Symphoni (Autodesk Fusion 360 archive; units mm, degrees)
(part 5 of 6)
sketch "Sketch36" plane through (0, 0, -41.2) normal (0, 0, -1) x axis (1, 0, 0)
  line L1 (80, 22.1729) -> (80, -17.8271)
  line L2 (40, 22.1729) -> (80, 22.1729)
  line L3 (40, -17.8271) -> (40, 22.1729)
  line L4 (80, -17.8271) -> (40, -17.8271)
  line L5 (31.4652, -4.8271) -> (42.4652, -4.8271)
  line L6 (31.4652, 9.1729) -> (31.4652, -4.8271)
  line L7 (42.4652, 9.1729) -> (31.4652, 9.1729)
  line L8 (42.4652, 13.4229) -> (42.4652, 9.1729)
  line L9 (76.9652, 13.4229) -> (42.4652, 13.4229)
  line L10 (78.9652, -7.0771) -> (78.9652, 11.4229)
  line L11 (42.4652, -9.0771) -> (76.9652, -9.0771)
  line L12 (42.4652, -4.8271) -> (42.4652, -9.0771)
  line L13 (34.9931, -0.7865) -> (34.9931, -0.3271)
  line L14 (37.9931, -0.7865) -> (34.9931, -0.7865)
  line L15 (37.9931, 5.2135) -> (37.9931, -0.7865)
  line L16 (34.9931, 5.2135) -> (37.9931, 5.2135)
  line L17 (34.9931, 4.6729) -> (34.9931, 5.2135)
  line L18 (33.9931, 4.6729) -> (34.9931, 4.6729)
  line L19 (33.9931, -0.3271) -> (33.9931, 4.6729)
  line L20 (34.9931, -0.3271) -> (33.9931, -0.3271)
  arc A1 centre (76.9652, 11.4229) radius 2 clockwise from (76.9652, 13.4229) to (78.9652, 11.4229)
  arc A2 centre (76.9652, -7.0771) radius 2 clockwise from (78.9652, -7.0771) to (76.9652, -9.0771)
  circle C1 centre (67.9652, 2.1729) radius 3.5
  circle C2 centre (56.9652, 2.1729) radius 2
  circle C3 centre (61.9652, 11.9229) radius 0.75
  circle C4 centre (76.9652, 11.4229) radius 1
  circle C5 centre (76.9652, -7.0771) radius 1
  circle C6 centre (61.9652, -7.5771) radius 0.75
  arc A3 centre (44.4652, -7.0771) radius 1.25 clockwise from (45.2016, -6.0671) to (44.1373, -5.8709)
  arc A4 centre (45.0652, -3.8212) radius 2.25 clockwise from (46.2076, -5.7597) to (45.2016, -6.0671)
  arc A5 centre (47.4652, -6.5771) radius 1.5 clockwise from (46.8283, -5.2191) to (46.2076, -5.7597)
  arc A6 centre (45.0652, -3.8212) radius 2.25 clockwise from (44.1373, -5.8709) to (46.8283, -5.2191)
  arc A7 centre (44.4652, 11.4229) radius 1.25 clockwise from (44.1373, 10.2167) to (45.2016, 10.4128)
  arc A8 centre (45.0652, 8.1669) radius 2.25 clockwise from (46.8283, 9.5648) to (44.1373, 10.2167)
  arc A9 centre (47.4652, 10.9229) radius 1.5 clockwise from (46.2076, 10.1054) to (46.8283, 9.5648)
  arc A10 centre (45.0652, 8.1669) radius 2.25 clockwise from (45.2016, 10.4128) to (46.2076, 10.1054)
  arc A11 centre (47.4652, 10.9229) radius 1.65 clockwise from (46.0818, 10.0236) to (46.7646, 9.429)
  arc A12 centre (44.4652, 11.4229) radius 1.4 clockwise from (44.0979, 10.0719) to (45.29, 10.2916)
  circle C7 centre (76.9652, -7.0771) radius 1.2
  circle C8 centre (76.9652, 11.4229) radius 1.2
  circle C9 centre (47.4652, 10.9229) radius 1.65
  circle C10 centre (44.4652, 11.4229) radius 1.4
  circle C11 centre (44.4652, 11.4229) radius 1.4
  circle C12 centre (47.4652, -6.5771) radius 1.65
  circle C13 centre (44.4652, -7.0771) radius 1.4
  circle C14 centre (81.4652, 2.1729) radius 1.25
  arc A13 centre (44.4652, -7.0771) radius 1.4 clockwise from (45.5356, -6.1747) to (45.8228, -6.7351)
  arc A14 centre (45.0652, -3.8212) radius 2.4 clockwise from (45.894, -6.0736) to (45.5356, -6.1747)
  arc A15 centre (47.4652, -6.5771) radius 1.65 clockwise from (45.8228, -6.7351) to (45.894, -6.0736)
  arc A16 centre (44.4652, -7.0771) radius 1.4 clockwise from (45.8604, -6.9604) to (43.7869, -5.8524)
  arc A17 centre (47.4652, -6.5771) radius 1.65 clockwise from (47.1824, -4.9516) to (45.8604, -6.9604)
  arc A18 centre (45.0652, -3.8212) radius 2.4 clockwise from (43.7869, -5.8524) to (47.1824, -4.9516)
  point P45 (46.0818, 10.0236)
  point P52 (45.894, -6.0736)
  point P54 (43.7869, -5.8524)
  concentric A9 C9
  coincident P45 C9
  concentric A7 C10
  concentric A7 C11
  concentric A5 C12
  coincident P52 C12
  concentric A3 C13
  coincident P54 C13
  dimension "d250" = 0.15
  dimension "d251" = 0.15
  dimension "d252" = 0.15
  dimension "d253" = 0.2
  dimension "d254" = 0.2
extrude "Extrude3" cut sketch "Sketch36" profile of C4 C5 A3 A4 A5 A6 A7 A8 A9 A10 A11 A12 A16 A17 C7 C8 C9 C10 C11 C12 C13 against normal blind 6
extrude "Extrude4" cut sketch "Sketch36" profile of C14 against normal blind 5
sketch "Sketch37" plane through (0, 0, -59.9956) normal (0, 0, 1) x axis (-1, 0, 0)
  line L1 (-85, 22.1729) -> (-85, -17.8271)
  line L2 (-96.2951, 22.1729) -> (-85, 22.1729)
  line L3 (-96.2951, -17.8271) -> (-96.2951, 22.1729)
  line L4 (-85, -17.8271) -> (-96.2951, -17.8271)
  circle C1 centre (-90.6476, 2.1729) radius 2.1
  circle C2 centre (-90.6476, 2.1729) radius 3
  concentric C1 C2
  dimension "d259" diameter C1 = 4.2
  dimension "d260" diameter C2 = 6
extrude "Extrude5" cut sketch "Sketch37" profile of C1 against normal blind 7
extrude "Extrude6" cut sketch "Sketch37" profile of C1 C2 against normal blind 1
split "Split2"
remove_body "RemoveBody6"
split "Split3"
sketch "Sketch38" plane through (0, 0, -65) normal (0, 0, -1) x axis (1, 0, 0)
  line L1 (11.5885, -27.6714) -> (11.5885, -22)
  line L2 (-11.2525, -22) -> (-11.2525, -27.8097)
  line L3 (11.5885, -22) -> (-11.2525, -22)
  circle C1 centre (-11.7533, -6.7858) radius 2.7
  circle C2 centre (11.7533, -6.7858) radius 2.7
  circle C3 centre (0, 13.5716) radius 2.7
  arc A1 centre (0, 0) radius 30 clockwise from (-11.2525, -27.8097) to (11.5885, -27.6714)
  circle C4 centre (0, 0) radius 30.3693
  point P1 (0, 0)
  point P10 (0, 0)
  coincident P1 P10
extrude "Extrude21" cut sketch "Sketch38" profile of C1 C2 C3 L1 A1 L2 L3 against normal blind 15
offset_faces "OffsetFaces3" distance -2
combine "Combine1"
fillet "Fillet1" radius 2
fillet "Fillet2" radius 2.5
fillet "Fillet3" radius 2.5
sketch "Sketch39" plane through (0, -22.1729, 0) normal (0, -1, 0) x axis (1, 0, 0)
  line L1 (96.2951, -64.9956) -> (82.5, -64.9956)
  line L2 (96.2951, -62.4956) -> (96.2951, -64.9956)
  line L3 (87, -59.9956) -> (93.7951, -59.9956)
  line L4 (85, -36.6938) -> (85, -57.9956)
  line L5 (30, -36.6938) -> (85, -36.6938)
  line L6 (20.208, -64.4069) -> (30, -36.6938)
  line L7 (20.208, -64.9956) -> (20.208, -64.4069)
  line L8 (37.5, -64.9956) -> (20.208, -64.9956)
  line L9 (40, -43.7) -> (40, -62.4956)
  line L10 (77.5, -41.2) -> (42.5, -41.2)
  line L11 (80, -62.4956) -> (80, -43.7)
  line L12 (47.9289, -41.2) -> (40, -49.3404)
  line L13 (80.0516, -43.7) -> (40, -43.7)
  line L14 (80.0516, -36.6938) -> (80.0516, -43.7)
  line L15 (40, -36.6938) -> (80.0516, -36.6938)
  line L16 (40, -43.7) -> (40, -36.6938)
  line L17 (60.0258, -43.7) -> (60.0258, -36.6938)
  line L18 (72.1227, -41.2) -> (80.0516, -49.3404)
  arc A1 centre (82.5, -62.4956) radius 2.5 clockwise from (82.5, -64.9956) to (80, -62.4956)
  arc A2 centre (93.7951, -62.4956) radius 2.5 clockwise from (93.7951, -59.9956) to (96.2951, -62.4956)
  arc A3 centre (87, -57.9956) radius 2 clockwise from (87, -59.9956) to (85, -57.9956)
  arc A4 centre (37.5, -62.4956) radius 2.5 clockwise from (40, -62.4956) to (37.5, -64.9956)
  arc A5 centre (42.5, -43.7) radius 2.5 clockwise from (40, -43.7) to (42.5, -41.2)
  arc A6 centre (77.5, -43.7) radius 2.5 clockwise from (77.5, -41.2) to (80, -43.7)
  circle C1 centre (32, -60) radius 1.6
  point P26 (40, -49.3404)
  point P27 (47.9289, -41.2)
  point P30 (80.0516, -36.6938)
  point P19 (40, -43.7)
  point P28 (40, -43.7)
  point P32 (60.0258, -36.6938)
  point P33 (60.0258, -43.7)
  point P34 (80.0516, -49.3404)
  point P35 (72.1227, -41.2)
  coincident L9 P26
  coincident L10 P27
  horizontal L13
  vertical L14
  horizontal L15
  vertical L16
  coincident L5 P30
  coincident P19 P28
  midpoint L15 P32
  midpoint L13 P33
  symmetric P26 L17 P34
  symmetric P27 L17 P35
extrude "Extrude22" new body sketch "Sketch39" profile of L9 A5 L10 A6 L11 L12 L13 L18 against normal blind 9
combine "Combine1"
offset_faces "OffsetFaces2" distance -2.1
work_plane "WorkPlane6"
work_plane "WorkPlane8" AlongDistance -5
sketch "Sketch40" plane through (0, -17.1729, 0) normal (0, -1, 0) x axis (-1, 0, 0)
  line L1 (-32, 56.7668) -> (-34.8, 58.3834)
  line L2 (-29.2, 58.3834) -> (-32, 56.7668)
  line L3 (-29.2, 61.6166) -> (-29.2, 58.3834)
  line L4 (-32, 63.2332) -> (-29.2, 61.6166)
  line L5 (-34.8, 61.6166) -> (-32, 63.2332)
  line L6 (-34.8, 58.3834) -> (-34.8, 61.6166)
  line L7 (-48.1073, 56.7668) -> (-32, 56.7668)
  line L8 (-48.1073, 63.2332) -> (-48.1073, 56.7668)
  line L9 (-32, 63.2332) -> (-48.1073, 63.2332)
  line L10 (-32, 56.7668) -> (-32, 63.2332)
  circle C1 centre (-32, 60) radius 1.6
  point P2 (-32, 60)
  point P9 (-32, 60)
  coincident P2 P9
  vertical L3
  horizontal L7
  vertical L8
  horizontal L9
  vertical L10
  dimension "d279" distance L3 L6 = 5.6
extrude "Extrude8" cut sketch "Sketch40" distance 2.62
mirror "Mirror1" mirrorStitchTolerance 0.1
sketch "Sketch41" plane through (0, 0, -36.6938) normal (0, 0, 1) x axis (-1, 0, 0)
  line L1 (-30, 0) -> (-30, -17.8271)
  line L2 (-30, 22.1729) -> (-30, 0)
  line L3 (-85, 22.1729) -> (-30, 22.1729)
  line L4 (-85, -17.8271) -> (-85, 22.1729)
  line L5 (-30, -17.8271) -> (-85, -17.8271)
  line L6 (-31.4652, -4.8271) -> (-42.4652, -4.8271)
  line L7 (-31.4652, 9.1729) -> (-31.4652, -4.8271)
  line L8 (-42.4652, 9.1729) -> (-31.4652, 9.1729)
  line L9 (-42.4652, 13.4229) -> (-42.4652, 9.1729)
  line L10 (-76.9652, 13.4229) -> (-42.4652, 13.4229)
  line L11 (-78.9652, -7.0771) -> (-78.9652, 11.4229)
  line L12 (-42.4652, -9.0771) -> (-76.9652, -9.0771)
  line L13 (-42.4652, -4.8271) -> (-42.4652, -9.0771)
  line L14 (-34.9931, -0.7865) -> (-34.9931, -0.3271)
  line L15 (-37.9931, -0.7865) -> (-34.9931, -0.7865)
  line L16 (-37.9931, 5.2135) -> (-37.9931, -0.7865)
  line L17 (-34.9931, 5.2135) -> (-37.9931, 5.2135)
  line L18 (-34.9931, 4.6729) -> (-34.9931, 5.2135)
  line L19 (-33.9931, 4.6729) -> (-34.9931, 4.6729)
  line L20 (-33.9931, -0.3271) -> (-33.9931, 4.6729)
  line L21 (-34.9931, -0.3271) -> (-33.9931, -0.3271)
  line L22 (-79.6652, -7.0771) -> (-79.6652, 11.4229)
  line L23 (-41.7652, -9.7771) -> (-76.9652, -9.7771)
  line L24 (-41.7652, -5.5271) -> (-41.7652, -9.7771)
  line L25 (-30.7652, -5.5271) -> (-41.7652, -5.5271)
  line L26 (-30.7652, 9.8729) -> (-30.7652, -5.5271)
  line L27 (-41.7652, 9.8729) -> (-30.7652, 9.8729)
  line L28 (-41.7652, 14.1229) -> (-41.7652, 9.8729)
  line L29 (-76.9652, 14.1229) -> (-41.7652, 14.1229)
  line L30 (-81.9652, -7.0771) -> (-81.9652, 11.4229)
  line L31 (-39.4652, -12.0771) -> (-76.9652, -12.0771)
  line L32 (-39.4652, -7.8271) -> (-39.4652, -12.0771)
  line L33 (-28.4652, -7.8271) -> (-39.4652, -7.8271)
  line L34 (-28.4652, 12.1729) -> (-28.4652, -7.8271)
  line L35 (-39.4652, 12.1729) -> (-28.4652, 12.1729)
  line L36 (-39.4652, 16.4229) -> (-39.4652, 12.1729)
  line L37 (-76.9652, 16.4229) -> (-39.4652, 16.4229)
  line L38 (-81.9652, 5.8898) -> (-79.6652, 5.8898)
  line L39 (-81.9652, -1.9652) -> (-81.9652, 5.8898)
  line L40 (-79.6652, -1.9652) -> (-81.9652, -1.9652)
  line L41 (-79.6652, 5.8898) -> (-79.6652, -1.9652)
  line L42 (-39.4652, -12.0771) -> (-39.4652, 16.4229)
  circle C1 centre (-81.4652, 2.1729) radius 1.25
  circle C2 centre (-76.9652, 11.4229) radius 1.2
  arc A1 centre (-47.4652, -6.5771) radius 1.65 clockwise from (-45.8604, -6.9604) to (-45.8228, -6.7351)
  arc A2 centre (-44.4652, -7.0771) radius 1.4 clockwise from (-45.8228, -6.7351) to (-45.8604, -6.9604)
  arc A3 centre (-44.4652, 11.4229) radius 1.4 clockwise from (-45.8604, 11.3061) to (-45.8228, 11.0809)
  arc A4 centre (-47.4652, 10.9229) radius 1.65 clockwise from (-45.8228, 11.0809) to (-45.8604, 11.3061)
  circle C3 centre (-76.9652, -7.0771) radius 1.2
  arc A5 centre (-76.9652, 11.4229) radius 2 clockwise from (-78.9652, 11.4229) to (-76.9652, 13.4229)
  arc A6 centre (-76.9652, -7.0771) radius 2 clockwise from (-76.9652, -9.0771) to (-78.9652, -7.0771)
  circle C4 centre (-67.9652, 2.1729) radius 3.5
  circle C5 centre (-56.9652, 2.1729) radius 2
  circle C6 centre (-61.9652, 11.9229) radius 0.75
  circle C7 centre (-76.9652, 11.4229) radius 1
  circle C8 centre (-76.9652, -7.0771) radius 1
  circle C9 centre (-61.9652, -7.5771) radius 0.75
  arc A7 centre (-44.4652, -7.0771) radius 1.25 clockwise from (-44.1373, -5.8709) to (-45.2016, -6.0671)
  arc A8 centre (-45.0652, -3.8212) radius 2.25 clockwise from (-45.2016, -6.0671) to (-46.2076, -5.7597)
  arc A9 centre (-47.4652, -6.5771) radius 1.5 clockwise from (-46.2076, -5.7597) to (-46.8283, -5.2191)
  arc A10 centre (-45.0652, -3.8212) radius 2.25 clockwise from (-46.8283, -5.2191) to (-44.1373, -5.8709)
  arc A11 centre (-44.4652, 11.4229) radius 1.25 clockwise from (-45.2016, 10.4128) to (-44.1373, 10.2167)
  arc A12 centre (-45.0652, 8.1669) radius 2.25 clockwise from (-44.1373, 10.2167) to (-46.8283, 9.5648)
  arc A13 centre (-47.4652, 10.9229) radius 1.5 clockwise from (-46.8283, 9.5648) to (-46.2076, 10.1054)
  arc A14 centre (-45.0652, 8.1669) radius 2.25 clockwise from (-46.2076, 10.1054) to (-45.2016, 10.4128)
  arc A15 centre (-76.9652, -7.0771) radius 2.7 clockwise from (-76.9652, -9.7771) to (-79.6652, -7.0771)
  arc A16 centre (-76.9652, 11.4229) radius 2.7 clockwise from (-79.6652, 11.4229) to (-76.9652, 14.1229)
  arc A17 centre (-76.9652, -7.0771) radius 5 clockwise from (-76.9652, -12.0771) to (-81.9652, -7.0771)
  arc A18 centre (-76.9652, 11.4229) radius 5 clockwise from (-81.9652, 11.4229) to (-76.9652, 16.4229)
  point P82 (-81.9652, -1.9652)
  point P80 (-79.6652, 5.8898)
  horizontal L38
  vertical L39
  horizontal L40
  vertical L41
  coincident L30 P82
  coincident L22 P80
  dimension "d284" = 0.7
  dimension "d285" = 3
extrude "Extrude9" add sketch "Sketch41" profile of A16 A15 L27 L25 L23 L22 L24 L28 L29 L30 A17 A18 L36 L32 L31 L37 L38 L40 L42 along normal blind 1.5
sketch "Sketch42" plane through (42.4652, 0, 0) normal (-1, 0, 0) x axis (0, -1, 0)
  line L1 (13.4229, -36.2) -> (9.1729, -36.2)
  line L2 (13.4229, -27.2) -> (13.4229, -36.2)
  line L3 (9.5319, -34.8072) -> (-6.1234, -34.8072)
  line L4 (9.5319, -39.723) -> (9.5319, -34.8072)
  line L5 (-6.1234, -39.723) -> (9.5319, -39.723)
  line L6 (-6.1234, -34.8072) -> (-6.1234, -39.723)
  arc A1 centre (1.7685, -27.2) radius 11.6544 clockwise from (13.4229, -27.2) to (9.1729, -36.2)
  horizontal L3
  vertical L4
  horizontal L5
  vertical L6
extrude "Extrude10" cut sketch "Sketch42" profile of A1 L1 L3 L4 L5 L6 along normal blind 13
work_plane "WorkPlane9" AlongDistance -28.796
split "Split3"
offset_faces "OffsetFaces1" distance 1.006
combine "Combine2"
combine "Combine2"
sketch "Sketch43" plane through (24.5652, 0, 0) normal (1, 0, 0) x axis (0, 1, 0)
  line L1 (-12.1972, -25.2) -> (-11.1736, -25.2)
  line L2 (-11.1736, -29.2) -> (-12.1972, -29.2)
  curve K1 (5.1979, -34.8072) -> (7.241, -23)
  curve K2 (7.241, -23) -> (4.8434, -19.2)
  line L3 (-9.1891, -19.2) -> (4.8434, -19.2)
  curve K3 (-9.1891, -19.2) -> (-11.5868, -23)
  curve K4 (-11.5868, -23) -> (-9.1891, -35.2)
  line L4 (5.1979, -35.2) -> (-9.1891, -35.2)
  line L5 (5.1979, -34.8072) -> (5.1979, -35.2)
  curve K5 (-11.8666, -22.8918) -> (-9.3174, -35.5)
  curve K6 (-9.3174, -18.9) -> (-11.8666, -22.8918)
  line L6 (-9.3174, -18.9) -> (4.9717, -18.9)
  curve K7 (7.5208, -22.8918) -> (4.9717, -18.9)
  curve K8 (5.4979, -34.9178) -> (7.5208, -22.8918)
  line L7 (5.4979, -34.9178) -> (5.4979, -35.5)
  line L8 (5.4979, -35.5) -> (-9.3174, -35.5)
  arc A1 centre (-11.1736, -27.2) radius 2 clockwise from (-11.1736, -25.2) to (-11.1736, -29.2)
  arc A2 centre (-0.7202, -27.2) radius 11.65 clockwise from (-12.1972, -29.2) to (-12.1972, -25.2)
  point P13 (-9.1891, -35.2)
  point P14 (-9.1891, -35.2)
  point P9 (5.1979, -34.8072)
  point P16 (5.1979, -34.8072)
  coincident P13 P14
  horizontal L4
  coincident P9 P16
  vertical L5
  dimension "d292" = 0.3
extrude "Extrude23" cut sketch "Sketch43" along normal blind 8 and against normal blind 4.5
fillet "Fillet3" radius 5
sketch "Sketch44" plane through (0, 0, -65) normal (0, 0, -1) x axis (1, 0, 0)
  line L1 (40, -27.6271) -> (11.6937, -27.6271)
  line L2 (40, -17.8271) -> (40, -27.6271)
  line L3 (24.1287, -17.8271) -> (40, -17.8271)
  line L4 (-11.2525, -22) -> (-11.2525, -27.8097)
  line L5 (11.5885, -22) -> (-11.2525, -22)
  line L6 (11.5885, -27.6714) -> (11.5885, -22)
  line L7 (0, 35) -> (0, 0)
  curve K1 (-8.9209, 28.6429) -> (-5, 35)
  curve K2 (8.9209, 28.6429) -> (5, 35)
  curve K3 (-5.1872, 34.0384) -> (-4.8128, 35.9616)
  curve K4 (-9.7824, 28.3746) -> (-8.0593, 28.9113)
  curve K5 (5.1872, 34.0384) -> (4.8128, 35.9616)
  curve K6 (9.7824, 28.3746) -> (8.0593, 28.9113)
  curve K7 (-28.6429, -8.9209) -> (-35, -5)
  curve K8 (-28.6429, 8.9209) -> (-35, 5)
  curve K9 (8.9209, -28.6429) -> (5, -35)
  curve K10 (-8.9209, -28.6429) -> (-5, -35)
  circle C1 centre (0, 13.5716) radius 2.7
  circle C2 centre (11.7533, -6.7858) radius 2.7
  circle C3 centre (-11.7533, -6.7858) radius 2.7
  arc A1 centre (0, 0) radius 30 clockwise from (-11.2525, -27.8097) to (24.1287, -17.8271)
  arc A2 centre (0, 0) radius 30 clockwise from (11.6937, -27.6271) to (11.5885, -27.6714)
  circle C4 centre (0, 35) radius 2
  circle C5 centre (0, 35) radius 5
  circle C6 centre (-35, 0) radius 5
  circle C7 centre (-35, 0) radius 2
  circle C8 centre (0, -35) radius 5
  circle C9 centre (0, -35) radius 2
  point P10 (0, 0)
  point P14 (0, 0)
  point P15 (0, 35)
  point P16 (0, 35)
  point P18 (-5, 35)
  point P19 (-8.9209, 28.6429)
  point P20 (5, 35)
  point P21 (8.9209, 28.6429)
  point P22 (-4.8128, 35.9616)
  point P26 (4.8128, 35.9616)
  point P23 (-5.1872, 34.0384)
  point P27 (5.1872, 34.0384)
  point P24 (-8.0593, 28.9113)
  point P28 (8.0593, 28.9113)
  point P25 (-9.7824, 28.3746)
  point P29 (9.7824, 28.3746)
  coincident P10 P14
  vertical L7
  coincident P15 P16
  concentric C4 C5
  tangent A1 C5
  coincident C5 P18
  coincident A1 P19
  tangent A1 K1
  tangent C5 K1
  midpoint P18 K3
  midpoint P19 K4
  symmetric L7 P18 P20
  symmetric L7 P19 P21
  symmetric L7 P22 P26
  symmetric L7 P23 P27
  symmetric L7 P24 P28
  symmetric L7 P25 P29
  dimension "d299" diameter C4 = 4
  dimension "d300" diameter C5 = 10
  dimension "d302" C-Pattern1-Angle = 180
extrude "Extrude24" add sketch "Sketch44" profile of A1 C4 C5 K1 K2 C6 C7 K7 K8 against normal blind 4
combine "Combine3"
offset_faces "OffsetFaces1" distance -2.46
sketch "Sketch45" plane through (41.4652, 0, 0) normal (1, 0, 0) x axis (0, 1, 0)
  line L1 (5.1979, -34.8072) -> (-9.5319, -34.8072)
  line L2 (-9.1891, -19.2) -> (4.8434, -19.2)
  line L3 (-9.5319, -34.8072) -> (-9.5319, -34.8208)
  curve K1 (-6.8356, -16.9333) -> (-6.3647, -17.2)
  line L4 (-6.3647, -17.2) -> (-4.7329, -17.2)
  line L5 (-4.7329, -17.9056) -> (-4.7329, -17.2)
  curve K2 (-3.9513, -18.2) -> (-4.7329, -17.9056)
  line L6 (-3.9513, -18.2) -> (0.3871, -18.2)
  line L7 (0.3871, -17.2) -> (0.3871, -18.2)
  line L8 (0.3871, -17.2) -> (2.9168, -17.2)
  curve K3 (3.3194, -17.4753) -> (2.9168, -17.2)
  curve K4 (3.331, -18.2) -> (3.3194, -17.4753)
  line L9 (3.331, -18.2) -> (4.1673, -18.2)
  curve K5 (4.1673, -18.2) -> (4.2157, -18.1824)
  curve K6 (7.5208, -22.8918) -> (4.2157, -18.1824)
  curve K7 (7.562, -23) -> (7.5208, -22.8918)
  line L10 (30, -23) -> (-30, -23)
  curve K8 (-11.8666, -22.8918) -> (-11.9078, -23)
  curve K9 (-7.7057, -17.5044) -> (-11.8666, -22.8918)
  curve K10 (-7.6984, -17.2) -> (-7.7057, -17.5044)
  line L11 (-7.6984, -17.2) -> (-7.2625, -17.2)
  curve K11 (-6.8356, -16.9333) -> (-7.2625, -17.2)
  line L12 (32.9, -15) -> (-32.9, -15)
  arc A1 centre (-3.6256, -27.2) radius 11.65 clockwise from (4.8434, -19.2) to (5.1979, -34.8072)
  arc A2 centre (-0.7202, -27.2) radius 11.65 clockwise from (-9.5319, -34.8208) to (-9.1891, -19.2)
  arc A3 centre (-2.1752, -23.8604) radius 8.5489 clockwise from (-8.5816, -18.2) to (4.2157, -18.1824)
  point P33 (-8.5816, -18.2)
  point P20 (4.2157, -18.1824)
  point P32 (4.2157, -18.1824)
  coincident K9 P33
  coincident P20 P32
extrude "Extrude25" cut sketch "Sketch45" profile of K1 L4 L5 K2 L6 L7 L8 K3 K4 L9 K5 L11 K11 A3 against normal blind 20
offset_faces "OffsetFaces2" distance -2
sketch "Sketch46" plane through (0, 0, 15) normal (0, 0, 1) x axis (-1, 0, 0)
  line L1 (11, -31.0066) -> (11, -5.7996)
  line L2 (-11, -5.7996) -> (-11, -31.0066)
  circle C1 centre (-24, 0) radius 2.5
  circle C2 centre (24, 0) radius 2.5
  circle C3 centre (12.3554, 12.0612) radius 1.5
  circle C4 centre (16.8554, -24.9388) radius 1.5
  circle C5 centre (-12.6446, 12.0612) radius 1.5
  circle C6 centre (-17.1446, -24.9388) radius 1.5
  arc A1 centre (0, 0) radius 12.4353 clockwise from (-11, -5.7996) to (11, -5.7996)
  arc A2 centre (0, 0) radius 32.9 clockwise from (-11, -31.0066) to (11, -31.0066)
  circle C7 centre (-24, 0) radius 2.5
  circle C8 centre (-17.0816, -24.9388) radius 1.5
  circle C9 centre (16.9184, -24.9388) radius 1.5
  circle C10 centre (24, 0) radius 2.5
  circle C11 centre (-24, 0) radius 2.5
  circle C12 centre (-24, 0) radius 2.5
extrude "Extrude20" cut sketch "Sketch46" against normal blind 6
position "Position11"
sketch "Sketch47" plane through (0, 0, -7.1) normal (0, 0, 1) x axis (-1, 0, 0)
  line L1 (-41.5194, 38.5136) -> (-41.6744, 38.8876)
  line L2 (-41.3299, 38.0803) -> (-41.5194, 38.5136)
  line L3 (-41.141, 37.6718) -> (-41.3299, 38.0803)
  line L4 (-40.9528, 37.2861) -> (-41.141, 37.6718)
  line L5 (-40.767, 36.9248) -> (-40.9528, 37.2861)
  line L6 (-40.5846, 36.5877) -> (-40.767, 36.9248)
  line L7 (-40.4066, 36.2746) -> (-40.5846, 36.5877)
  line L8 (-40.2345, 35.986) -> (-40.4066, 36.2746)
  line L9 (-40.0674, 35.7187) -> (-40.2345, 35.986)
  line L10 (-39.8106, 35.3316) -> (-40.0674, 35.7187)
  line L11 (-39.7541, 35.2368) -> (-39.8106, 35.3316)
  line L12 (-39.7187, 35.1556) -> (-39.7541, 35.2368)
  line L13 (-39.7039, 35.0886) -> (-39.7187, 35.1556)
  line L14 (-39.7089, 35.0369) -> (-39.7039, 35.0886)
  line L15 (-39.7187, 35.017) -> (-39.7089, 35.0369)
  line L16 (-39.7913, 34.9338) -> (-39.7187, 35.017)
  line L17 (-40.2448, 34.4101) -> (-39.7913, 34.9338)
  line L18 (-40.6917, 33.8808) -> (-40.2448, 34.4101)
  line L19 (-40.7626, 33.7961) -> (-40.6917, 33.8808)
  line L20 (-40.7807, 33.7834) -> (-40.7626, 33.7961)
  line L21 (-40.831, 33.7703) -> (-40.7807, 33.7834)
  line L22 (-40.8994, 33.7746) -> (-40.831, 33.7703)
  line L23 (-40.9852, 33.797) -> (-40.8994, 33.7746)
  line L24 (-41.0877, 33.8381) -> (-40.9852, 33.797)
  line L25 (-41.5099, 34.0316) -> (-41.0877, 33.8381)
  line L26 (-41.7999, 34.1551) -> (-41.5099, 34.0316)
  line L27 (-42.1117, 34.2803) -> (-41.7999, 34.1551)
  line L28 (-42.4487, 34.4075) -> (-42.1117, 34.2803)
  line L29 (-42.8101, 34.5353) -> (-42.4487, 34.4075)
  line L30 (-43.1959, 34.6628) -> (-42.8101, 34.5353)
  line L31 (-43.6061, 34.7888) -> (-43.1959, 34.6628)
  line L32 (-44.039, 34.9119) -> (-43.6061, 34.7888)
  line L33 (-44.4965, 35.0317) -> (-44.039, 34.9119)
  line L34 (-44.89, 35.1267) -> (-44.4965, 35.0317)
  line L35 (-45.6389, 33.5297) -> (-45.8356, 33.8836)
  line L36 (-45.4013, 33.1209) -> (-45.6389, 33.5297)
  line L37 (-45.1671, 32.7365) -> (-45.4013, 33.1209)
  line L38 (-44.9362, 32.3748) -> (-45.1671, 32.7365)
  line L39 (-44.7104, 32.037) -> (-44.9362, 32.3748)
  line L40 (-44.4908, 31.7229) -> (-44.7104, 32.037)
  line L41 (-44.2782, 31.4321) -> (-44.4908, 31.7229)
  line L42 (-44.0743, 31.165) -> (-44.2782, 31.4321)
  line L43 (-43.8778, 30.9185) -> (-44.0743, 31.165)
  line L44 (-43.5787, 30.5633) -> (-43.8778, 30.9185)
  line L45 (-43.5117, 30.4755) -> (-43.5787, 30.5633)
  line L46 (-43.4673, 30.3988) -> (-43.5117, 30.4755)
  line L47 (-43.4449, 30.334) -> (-43.4673, 30.3988)
  line L48 (-43.444, 30.2821) -> (-43.4449, 30.334)
  line L49 (-43.4514, 30.2612) -> (-43.444, 30.2821)
  line L50 (-43.5141, 30.1702) -> (-43.4514, 30.2612)
  line L51 (-43.9049, 29.5983) -> (-43.5141, 30.1702)
  line L52 (-44.2886, 29.0215) -> (-43.9049, 29.5983)
  line L53 (-44.3493, 28.9292) -> (-44.2886, 29.0215)
  line L54 (-44.3659, 28.9145) -> (-44.3493, 28.9292)
  line L55 (-44.4144, 28.8958) -> (-44.3659, 28.9145)
  line L56 (-44.4829, 28.8923) -> (-44.4144, 28.8958)
  line L57 (-44.5706, 28.9047) -> (-44.4829, 28.8923)
  line L58 (-44.6771, 28.9339) -> (-44.5706, 28.9047)
  line L59 (-45.1186, 29.078) -> (-44.6771, 28.9339)
  line L60 (-45.4208, 29.1677) -> (-45.1186, 29.078)
  line L61 (-45.7449, 29.2565) -> (-45.4208, 29.1677)
  line L62 (-46.0942, 29.3445) -> (-45.7449, 29.2565)
  line L63 (-46.4678, 29.4302) -> (-46.0942, 29.3445)
  line L64 (-46.8656, 29.5129) -> (-46.4678, 29.4302)
  line L65 (-47.2875, 29.5913) -> (-46.8656, 29.5129)
  line L66 (-47.7316, 29.6642) -> (-47.2875, 29.5913)
  line L67 (-48.1997, 29.7311) -> (-47.7316, 29.6642)
  line L68 (-48.6016, 29.7807) -> (-48.1997, 29.7311)
  line L69 (-49.1635, 28.1087) -> (-49.3992, 28.4379)
  line L70 (-48.8809, 27.7296) -> (-49.1635, 28.1087)
  line L71 (-48.6044, 27.3745) -> (-48.8809, 27.7296)
  line L72 (-48.3337, 27.0414) -> (-48.6044, 27.3745)
  line L73 (-48.0709, 26.7316) -> (-48.3337, 27.0414)
  line L74 (-47.8169, 26.4446) -> (-48.0709, 26.7316)
  line L75 (-47.5726, 26.1799) -> (-47.8169, 26.4446)
  line L76 (-47.3396, 25.9378) -> (-47.5726, 26.1799)
  line L77 (-47.1163, 25.7153) -> (-47.3396, 25.9378)
  line L78 (-46.7785, 25.3965) -> (-47.1163, 25.7153)
  line L79 (-46.702, 25.3169) -> (-46.7785, 25.3965)
  line L80 (-46.6491, 25.2458) -> (-46.702, 25.3169)
  line L81 (-46.6195, 25.184) -> (-46.6491, 25.2458)
  line L82 (-46.6127, 25.1325) -> (-46.6195, 25.184)
  line L83 (-46.6177, 25.1108) -> (-46.6127, 25.1325)
  line L84 (-46.6696, 25.0134) -> (-46.6177, 25.1108)
  line L85 (-46.9927, 24.4006) -> (-46.6696, 25.0134)
  line L86 (-47.3081, 23.7838) -> (-46.9927, 24.4006)
  line L87 (-47.3579, 23.6852) -> (-47.3081, 23.7838)
  line L88 (-47.3727, 23.6687) -> (-47.3579, 23.6852)
  line L89 (-47.4188, 23.6446) -> (-47.3727, 23.6687)
  line L90 (-47.4864, 23.6333) -> (-47.4188, 23.6446)
  line L91 (-47.575, 23.6356) -> (-47.4864, 23.6333)
  line L92 (-47.6841, 23.6525) -> (-47.575, 23.6356)
  line L93 (-48.1392, 23.7453) -> (-47.6841, 23.6525)
  line L94 (-48.4496, 23.8) -> (-48.1392, 23.7453)
  line L95 (-48.7817, 23.8513) -> (-48.4496, 23.8)
  line L96 (-49.1388, 23.8988) -> (-48.7817, 23.8513)
  line L97 (-49.5197, 23.9415) -> (-49.1388, 23.8988)
  line L98 (-49.9243, 23.9782) -> (-49.5197, 23.9415)
  line L99 (-50.3524, 24.008) -> (-49.9243, 23.9782)
  line L100 (-50.8019, 24.0299) -> (-50.3524, 24.008)
  line L101 (-51.2746, 24.043) -> (-50.8019, 24.0299)
  line L102 (-51.6795, 24.0464) -> (-51.2746, 24.043)
  line L103 (-52.0472, 22.3213) -> (-52.3189, 22.6215)
  line L104 (-51.7232, 21.9768) -> (-52.0472, 22.3213)
  line L105 (-51.408, 21.6555) -> (-51.7232, 21.9768)
  line L106 (-51.1012, 21.3556) -> (-51.408, 21.6555)
  line L107 (-50.8048, 21.0777) -> (-51.1012, 21.3556)
  line L108 (-50.5197, 20.8215) -> (-50.8048, 21.0777)
  line L109 (-50.2468, 20.5864) -> (-50.5197, 20.8215)
  line L110 (-49.9877, 20.3724) -> (-50.2468, 20.5864)
  line L111 (-49.7405, 20.1768) -> (-49.9877, 20.3724)
  line L112 (-49.3686, 19.8986) -> (-49.7405, 20.1768)
  line L113 (-49.2835, 19.8283) -> (-49.3686, 19.8986)
  line L114 (-49.2229, 19.7636) -> (-49.2835, 19.8283)
  line L115 (-49.1864, 19.7056) -> (-49.2229, 19.7636)
  line L116 (-49.1737, 19.6552) -> (-49.1864, 19.7056)
  line L117 (-49.1763, 19.6331) -> (-49.1737, 19.6552)
  line L118 (-49.2167, 19.5304) -> (-49.1763, 19.6331)
  line L119 (-49.4679, 18.8848) -> (-49.2167, 19.5304)
  line L120 (-49.7108, 18.236) -> (-49.4679, 18.8848)
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offset_faces "OffsetFaces3" distance -5
combine "Combine1"
sketch "Sketch48" plane through (0, 0, 13) normal (0, 0, 1) x axis (-1, 0, 0)
  circle C1 centre (0, 0) radius 50.7671
  circle C2 centre (0, 0) radius 48.4417
  circle C3 centre (0, 0) radius 53.6774
  circle C4 centre (0, 0) radius 53.1163
extrude "Extrude2" cut sketch "Sketch48" against normal blind 2
split "Split2"
remove_body "RemoveBody1"
delete_face "DeleteFace1"
delete_face "DeleteFace2"
sketch "Sketch49" plane through (0, 0, 11) normal (0, 0, 1) x axis (-1, 0, 0)
  circle C1 centre (0, 0) radius 48.4417
  circle C2 centre (0, 0) radius 53.6774
  circle C3 centre (0, 0) radius 48.4417
  circle C4 centre (0, 0) radius 53.6774
  circle C5 centre (0, 0) radius 51.7038
  circle C6 centre (0, 0) radius 50.4062
  concentric C1 C3
  concentric C1 C4
  concentric C4 C5
  concentric C1 C6
extrude "Extrude3" add sketch "Sketch49" profile of C5 C6 along normal blind 3
delete_face "DeleteFace1"
delete_face "DeleteFace2"
sketch "Sketch50" plane through (0, 0, -65) normal (0, 0, -1) x axis (1, 0, 0)
  line L1 (40, -27.6271) -> (11.6937, -27.6271)
  line L2 (40, -17.8271) -> (40, -27.6271)
  line L3 (24.1287, -17.8271) -> (40, -17.8271)
  curve K1 (8.9209, 28.6429) -> (5, 35)
  curve K2 (-8.9209, 28.6429) -> (-5, 35)
  curve K3 (-28.6429, 8.9209) -> (-35, 5)
  curve K4 (-28.6429, -8.9209) -> (-35, -5)
  line L4 (-11.2525, -22) -> (-11.2525, -27.8097)
  line L5 (11.5885, -22) -> (-11.2525, -22)
  line L6 (11.5885, -27.6714) -> (11.5885, -22)
  circle C1 centre (-35, 0) radius 2
  circle C2 centre (0, 35) radius 2
  circle C3 centre (0, 13.5716) radius 2.7
  circle C4 centre (11.7533, -6.7858) radius 2.7
  circle C5 centre (-11.7533, -6.7858) radius 2.7
  arc A1 centre (0, 0) radius 30 clockwise from (8.9209, 28.6429) to (24.1287, -17.8271)
  arc A2 centre (0, 35) radius 5 clockwise from (-5, 35) to (5, 35)
  arc A3 centre (0, 0) radius 30 clockwise from (-28.6429, 8.9209) to (-8.9209, 28.6429)
  arc A4 centre (-35, 0) radius 5 clockwise from (-35, -5) to (-35, 5)
  arc A5 centre (0, 0) radius 30 clockwise from (-11.2525, -27.8097) to (-28.6429, -8.9209)
  arc A6 centre (0, 0) radius 30 clockwise from (11.6937, -27.6271) to (11.5885, -27.6714)
chamfer "Chamfer1" distance 5
sketch "Sketch51" plane through (0, 0, -15) normal (0, 0, -1) x axis (1, 0, 0)
  line L1 (40.2131, 39.8756) -> (40.5933, 40.0148)
  line L2 (39.7723, 39.7044) -> (40.2131, 39.8756)
  line L3 (39.3562, 39.5327) -> (39.7723, 39.7044)
  line L4 (38.963, 39.3608) -> (39.3562, 39.5327)
  line L5 (38.5943, 39.1902) -> (38.963, 39.3608)
  line L6 (38.2499, 39.022) -> (38.5943, 39.1902)
  line L7 (37.9296, 38.8573) -> (38.2499, 39.022)
  line L8 (37.6341, 38.6973) -> (37.9296, 38.8573)
  line L9 (37.36, 38.5415) -> (37.6341, 38.6973)
  line L10 (36.9626, 38.3012) -> (37.36, 38.5415)
  line L11 (36.8655, 38.2486) -> (36.9626, 38.3012)
  line L12 (36.7828, 38.2167) -> (36.8655, 38.2486)
  line L13 (36.7153, 38.2046) -> (36.7828, 38.2167)
  line L14 (36.6639, 38.2118) -> (36.7153, 38.2046)
  line L15 (36.6444, 38.2224) -> (36.6639, 38.2118)
  line L16 (36.5643, 38.2985) -> (36.6444, 38.2224)
  line L17 (36.06, 38.7734) -> (36.5643, 38.2985)
  line L18 (35.5498, 39.242) -> (36.06, 38.7734)
  line L19 (35.4681, 39.3164) -> (35.5498, 39.242)
  line L20 (35.4562, 39.335) -> (35.4681, 39.3164)
  line L21 (35.4453, 39.3858) -> (35.4562, 39.335)
  line L22 (35.4524, 39.454) -> (35.4453, 39.3858)
  line L23 (35.4783, 39.5388) -> (35.4524, 39.454)
  line L24 (35.5236, 39.6394) -> (35.4783, 39.5388)
  line L25 (35.7346, 40.0532) -> (35.5236, 39.6394)
  line L26 (35.8701, 40.3378) -> (35.7346, 40.0532)
  line L27 (36.0083, 40.6441) -> (35.8701, 40.3378)
  line L28 (36.1494, 40.9755) -> (36.0083, 40.6441)
  line L29 (36.2922, 41.3312) -> (36.1494, 40.9755)
  line L30 (36.4356, 41.7114) -> (36.2922, 41.3312)
  line L31 (36.5786, 42.116) -> (36.4356, 41.7114)
  line L32 (36.7197, 42.5434) -> (36.5786, 42.116)
  line L33 (36.8585, 42.9954) -> (36.7197, 42.5434)
  line L34 (36.9699, 43.3847) -> (36.8585, 42.9954)
  line L35 (35.4055, 44.1996) -> (35.7673, 44.3813)
  line L36 (34.9871, 43.9793) -> (35.4055, 44.1996)
  line L37 (34.5933, 43.7613) -> (34.9871, 43.9793)
  line L38 (34.2223, 43.5457) -> (34.5933, 43.7613)
  line L39 (33.8754, 43.3342) -> (34.2223, 43.5457)
  line L40 (33.5524, 43.1278) -> (33.8754, 43.3342)
  line L41 (33.253, 42.9276) -> (33.5524, 43.1278)
  line L42 (32.9776, 42.7351) -> (33.253, 42.9276)
  line L43 (32.7231, 42.549) -> (32.9776, 42.7351)
  line L44 (32.3557, 42.2649) -> (32.7231, 42.549)
  line L45 (32.2652, 42.2017) -> (32.3557, 42.2649)
  line L46 (32.1867, 42.1605) -> (32.2652, 42.2017)
  line L47 (32.121, 42.1408) -> (32.1867, 42.1605)
  line L48 (32.0691, 42.1421) -> (32.121, 42.1408)
  line L49 (32.0485, 42.1504) -> (32.0691, 42.1421)
  line L50 (31.9603, 42.2168) -> (32.0485, 42.1504)
  line L51 (31.4051, 42.6312) -> (31.9603, 42.2168)
  line L52 (30.8448, 43.0386) -> (31.4051, 42.6312)
  line L53 (30.7552, 43.1031) -> (30.8448, 43.0386)
  line L54 (30.7412, 43.1203) -> (30.7552, 43.1031)
  line L55 (30.7246, 43.1696) -> (30.7412, 43.1203)
  line L56 (30.7239, 43.2381) -> (30.7246, 43.1696)
  line L57 (30.74, 43.3253) -> (30.7239, 43.2381)
  line L58 (30.7735, 43.4304) -> (30.74, 43.3253)
  line L59 (30.9359, 43.8655) -> (30.7735, 43.4304)
  line L60 (31.0382, 44.1638) -> (30.9359, 43.8655)
  line L61 (31.1405, 44.4838) -> (31.0382, 44.1638)
  line L62 (31.2429, 44.8291) -> (31.1405, 44.4838)
  line L63 (31.3442, 45.1988) -> (31.2429, 44.8291)
  line L64 (31.4434, 45.5928) -> (31.3442, 45.1988)
  line L65 (31.5393, 46.0111) -> (31.4434, 45.5928)
  line L66 (31.6308, 46.4518) -> (31.5393, 46.0111)
  line L67 (31.7171, 46.9167) -> (31.6308, 46.4518)
  line L68 (31.7834, 47.3161) -> (31.7171, 46.9167)
  line L69 (30.1364, 47.9474) -> (30.4751, 48.1692)
  line L70 (29.7458, 47.6808) -> (30.1364, 47.9474)
  line L71 (29.3794, 47.4194) -> (29.7458, 47.6808)
  line L72 (29.0354, 47.1629) -> (29.3794, 47.4194)
  line L73 (28.7149, 46.9132) -> (29.0354, 47.1629)
  line L74 (28.4175, 46.6714) -> (28.7149, 46.9132)
  line L75 (28.1428, 46.4384) -> (28.4175, 46.6714)
  line L76 (27.8912, 46.2157) -> (28.1428, 46.4384)
  line L77 (27.6596, 46.0018) -> (27.8912, 46.2157)
  line L78 (27.3269, 45.6777) -> (27.6596, 46.0018)
  line L79 (27.2442, 45.6046) -> (27.3269, 45.6777)
  line L80 (27.171, 45.5547) -> (27.2442, 45.6046)
  line L81 (27.108, 45.5277) -> (27.171, 45.5547)
  line L82 (27.0562, 45.523) -> (27.108, 45.5277)
  line L83 (27.0348, 45.5289) -> (27.0562, 45.523)
  line L84 (26.9396, 45.5849) -> (27.0348, 45.5289)
  line L85 (26.3408, 45.9332) -> (26.9396, 45.5849)
  line L86 (25.7377, 46.2741) -> (26.3408, 45.9332)
  line L87 (25.6414, 46.328) -> (25.7377, 46.2741)
  line L88 (25.6255, 46.3435) -> (25.6414, 46.328)
  line L89 (25.6033, 46.3905) -> (25.6255, 46.3435)
  line L90 (25.5949, 46.4585) -> (25.6033, 46.3905)
  line L91 (25.6009, 46.547) -> (25.5949, 46.4585)
  line L92 (25.6223, 46.6553) -> (25.6009, 46.547)
  line L93 (25.734, 47.106) -> (25.6223, 46.6553)
  line L94 (25.8016, 47.414) -> (25.734, 47.106)
  line L95 (25.8667, 47.7436) -> (25.8016, 47.414)
  line L96 (25.9291, 48.0984) -> (25.8667, 47.7436)
  line L97 (25.9876, 48.4772) -> (25.9291, 48.0984)
  line L98 (26.0412, 48.8799) -> (25.9876, 48.4772)
  line L99 (26.0889, 49.3064) -> (26.0412, 48.8799)
  line L100 (26.1295, 49.7546) -> (26.0889, 49.3064)
  line L101 (26.1623, 50.2264) -> (26.1295, 49.7546)
  line L102 (26.1826, 50.6307) -> (26.1623, 50.2264)
  line L103 (24.4743, 51.0702) -> (24.7856, 51.3291)
  line L104 (24.1167, 50.7608) -> (24.4743, 51.0702)
  line L105 (23.7825, 50.4593) -> (24.1167, 50.7608)
  line L106 (23.47, 50.1652) -> (23.7825, 50.4593)
  line L107 (23.18, 49.8807) -> (23.47, 50.1652)
  line L108 (22.9121, 49.6065) -> (23.18, 49.8807)
  line L109 (22.6658, 49.3437) -> (22.9121, 49.6065)
  line L110 (22.4412, 49.0938) -> (22.6658, 49.3437)
  line L111 (22.2355, 48.8549) -> (22.4412, 49.0938)
  line L112 (21.9419, 48.495) -> (22.2355, 48.8549)
  line L113 (21.8681, 48.4129) -> (21.9419, 48.495)
  line L114 (21.801, 48.355) -> (21.8681, 48.4129)
  line L115 (21.7415, 48.321) -> (21.801, 48.355)
  line L116 (21.6906, 48.3104) -> (21.7415, 48.321)
  line L117 (21.6687, 48.3139) -> (21.6906, 48.3104)
  line L118 (21.5677, 48.3586) -> (21.6687, 48.3139)
  line L119 (20.9331, 48.6365) -> (21.5677, 48.3586)
  line L120 (20.2951, 48.9063) -> (20.9331, 48.6365)
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extrude "Extrude4" cut sketch "Sketch51" against normal blind 8
sketch "Sketch52" plane through (0, 0, -7.1) normal (0, 0, 1) x axis (-1, 0, 0)
  line L1 (-53.63, 6.1344) -> (-53.3196, 6.1872)
  line L2 (-53.96, 6.0711) -> (-53.63, 6.1344)
  line L3 (-54.3122, 5.9959) -> (-53.96, 6.0711)
  line L4 (-54.6853, 5.9081) -> (-54.3122, 5.9959)
  line L5 (-55.0788, 5.8067) -> (-54.6853, 5.9081)
  line L6 (-55.492, 5.6909) -> (-55.0788, 5.8067)
  line L7 (-55.9228, 5.5605) -> (-55.492, 5.6909)
  line L8 (-56.3724, 5.4139) -> (-55.9228, 5.5605)
  line L9 (-56.7548, 5.2811) -> (-56.3724, 5.4139)
  line L10 (-56.5214, 3.5327) -> (-56.8782, 3.7241)
  line L11 (-56.1005, 3.3172) -> (-56.5214, 3.5327)
  line L12 (-55.6957, 3.1205) -> (-56.1005, 3.3172)
  line L13 (-55.3059, 2.9411) -> (-55.6957, 3.1205)
  line L14 (-54.9333, 2.779) -> (-55.3059, 2.9411)
  line L15 (-54.5787, 2.6335) -> (-54.9333, 2.779)
  line L16 (-54.2427, 2.5038) -> (-54.5787, 2.6335)
  line L17 (-53.9268, 2.3893) -> (-54.2427, 2.5038)
  line L18 (-53.6286, 2.2883) -> (-53.9268, 2.3893)
  arc A1 centre (0, 0) radius 53.6774 clockwise from (-53.6286, 2.2883) to (-53.3196, 6.1872)
  arc A2 centre (0, 0) radius 57 clockwise from (-56.8782, 3.7241) to (-56.7548, 5.2811)
  circle C1 centre (0, 0) radius 52.9546
  concentric A2 C1
offset_faces "OffsetFaces4" distance -1
offset_faces "OffsetFaces4" distance 0.1
sketch "Sketch31" plane through (0, -2.1729, 0) normal (0, 1, 0) x axis (1, 0, 0)
  line L1 (43, 38.5816) -> (30.1191, 38.5816)
  line L2 (43, 36.3257) -> (43, 38.5816)
  line L3 (85, 36.3257) -> (43, 36.3257)
  line L4 (85, 65) -> (85, 36.3257)
  line L5 (80, 65) -> (85, 65)
  line L6 (80, 40) -> (80, 65)
  line L7 (45, 40) -> (80, 40)
  line L8 (45, 65) -> (45, 40)
  line L9 (30, 65) -> (45, 65)
  horizontal L1
  perpendicular L1 L2
  perpendicular L2 L3
  perpendicular L3 L4
  perpendicular L2 L5
  perpendicular L5 L6
  perpendicular L6 L7
  perpendicular L7 L8
  perpendicular L8 L9
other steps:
base_feature "Base Feature1"
base_feature "Base Feature1"
base_feature "Base Feature1"
base_feature "Base Feature1"
base_feature "Base Feature1" bodies "G1"
split "Split1"
extrude "Extrude2" cut sketch "Sketch35" profile of C1 against normal blind 69
extrude "Extrude7" cut sketch "Sketch38" profile of C1 C2 C3 L1 A1 L2 L3 against normal blind 15
split "Split1"
extrude "Extrude6" cut sketch "Sketch3" profile of A1 L1 L2 L3 L4 L5 L6 C5 blind -20 from offset -50
extrude "Extrude19" cut sketch "Sketch35" profile of C1 against normal blind 69
create_component "CreateComponent1"
create_component "CreateComponent3"
create_component "CreateComponent4"
create_component "CreateComponent5"
remove_body "RemoveBody1"
create_component "CreateComponent6"
remove_body "RemoveBody2"
joint_origin "JointOrigin2"
joint_origin "JointOrigin2"
create_component "CreateComponent2"
remove_body "RemoveBody2"
create_component "CreateComponent9"
remove_body "RemoveBody3"
create_component "CreateComponent10"
remove_body "RemoveBody4"
joint_origin "JointOrigin2"
joint_origin "JointOrigin2"
create_component "CreateComponent1"
remove_body "RemoveBody7"
remove_body "RemoveBody8"
remove_body "RemoveBody2"
remove_body "RemoveBody2"
named bodies: "Lower Half", "Upper Half", "G1", "Lower Half (1)", "Lower Half (2)"

design "Symphony_Power"
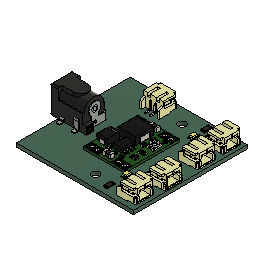
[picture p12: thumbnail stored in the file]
description: KiCad electronic assembly
part number: Symphony_Power 1
description: Part Number
part number: Base
part number: Emmiter
part number: Contact_1
part number: Contact_2
part number: LED-1206
part number: S2B-PH-SM4-TB_LF__SN_
part number: Ceramic
part number: Contacts
part number: Contacts (Mirror #1)
base_feature "Base Feature1"
base_feature "Base Feature1"
base_feature "Base Feature1"
base_feature "Base Feature1"
base_feature "Base Feature1"
base_feature "Base Feature1"
base_feature "Base Feature1"
base_feature "Base Feature1"
base_feature "Base Feature1"
base_feature "Base Feature1"
base_feature "Base Feature1"
base_feature "Base Feature1"
base_feature "Base Feature1"
base_feature "Base Feature1"
base_feature "Base Feature1"
base_feature "Base Feature1"
base_feature "Base Feature1"
base_feature "Base Feature1"
base_feature "Base Feature1"
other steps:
create_component "CreateComponent1"
create_component "CreateComponent1"
create_component "CreateComponent2"
create_component "CreateComponent3"
create_component "CreateComponent4"
create_component "CreateComponent2"
create_component "CreateComponent3"
create_component "CreateComponent1"
create_component "CreateComponent2"
create_component "CreateComponent3"
create_component "CreateComponent4"
create_component "CreateComponent4"
create_component "CreateComponent5"
create_component "CreateComponent1"
create_component "CreateComponent2"
create_component "CreateComponent3"
create_component "CreateComponent6"
create_component "CreateComponent1"
create_component "CreateComponent2"
create_component "CreateComponent3"
create_component "CreateComponent4"
create_component "CreateComponent5"
create_component "CreateComponent7"

design "Playback_Controls"
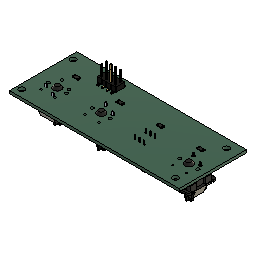
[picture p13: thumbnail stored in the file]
description: KiCad electronic assembly
part number: Playback_Controls 1
description: Part Number
part number: Ceramic
part number: Contacts
part number: Contacts (Mirror #1)
part number: Overcoat
part number: Resistor-1206
part number: PinHeader_2x04_P2.54mm_Vertical_SMD
part number: MX1A-11NN
part number: SW_Btn_XLX
part number: Playback_Controls_PCB
base_feature "Base Feature1"
base_feature "Base Feature1"
base_feature "Base Feature1"
base_feature "Base Feature1"
base_feature "Base Feature1"
base_feature "Base Feature1"
base_feature "Base Feature1"
base_feature "Base Feature1"
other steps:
create_component "CreateComponent1"
create_component "CreateComponent1"
create_component "CreateComponent2"
create_component "CreateComponent3"
create_component "CreateComponent4"
create_component "CreateComponent2"
create_component "CreateComponent3"
create_component "CreateComponent4"
create_component "CreateComponent5"

design "Back Panel" references "Symphoni_BL_Speaker_Copy", "Symphony_Power"
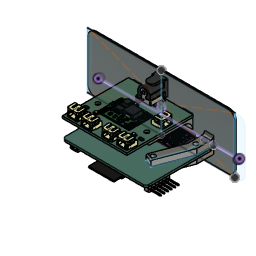
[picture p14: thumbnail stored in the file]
sketch "Sketch1" plane through (0, 0, 0) normal (0, 1, 0) x axis (1, 0, 0)
  line L1 (110, 0) -> (0, 0)
  line L2 (110, -40) -> (110, 0)
  line L3 (0, -40) -> (110, -40)
  line L4 (0, 0) -> (0, -40)
  line L5 (110, -20) -> (0, -20)
  line L6 (55, -40) -> (55, 0)
  line L7 (82.5, -25) -> (82.5, 0)
  line L8 (27.5, -25) -> (27.5, 0)
  point P1 (0, 0)
  point P2 (0, 0)
  point P6 (0, -20)
  point P7 (110, -20)
  point P8 (55, 0)
  point P9 (55, -40)
  point P10 (82.5, 0)
  point P12 (27.5, 0)
  point P11 (82.5, -25)
  point P13 (27.5, -25)
  point P14 (55, -8.6888)
  point P15 (55, -32.7017)
  point P3 (110, 0)
  point P5 (0, -40)
  horizontal L1
  vertical L2
  horizontal L3
  vertical L4
  coincident P1 P2
  midpoint L4 P6
  midpoint L2 P7
  midpoint L1 P8
  midpoint L3 P9
  coincident L1 P10
  perpendicular L5 L7
  symmetric L6 P10 P12
  symmetric L6 P11 P13
  coincident L6 P14
  coincident L6 P15
  dimension "d1" distance P2 P3 = 110
  dimension "d2" distance P2 P5 = 40
component_insert "Component Insert1"
extrude "Extrude1" new body sketch "Sketch1" profile of L1 L2 L3 L4 against normal blind 1
component_insert "Component Insert2"
position "Position1"
sketch "Sketch2" plane through (0, 0, 0) normal (0, 1, 0) x axis (1, 0, 0)
  line L1 (54.45, -26.1017) -> (54.45, -36.5017)
  line L2 (53.95, -37.0017) -> (46.05, -37.0017)
  line L3 (45.55, -36.5017) -> (45.55, -26.1017)
  line L4 (45.55, -26.1017) -> (54.45, -26.1017)
  line L5 (54.65, -25.9017) -> (54.65, -36.5017)
  line L6 (45.35, -25.9017) -> (54.65, -25.9017)
  line L7 (45.35, -36.5017) -> (45.35, -25.9017)
  line L8 (53.95, -37.2017) -> (46.05, -37.2017)
  line L9 (0, -40) -> (110, -40)
  line L10 (0, 0) -> (0, -40)
  line L11 (110, -40) -> (110, 0)
  line L12 (110, 0) -> (0, 0)
  line L13 (50, -26.321) -> (50, -18.6888)
  circle C1 centre (50, -18.6888) radius 2.5
  arc A1 centre (53.95, -36.5017) radius 0.5 clockwise from (54.45, -36.5017) to (53.95, -37.0017)
  arc A2 centre (46.05, -36.5017) radius 0.5 clockwise from (46.05, -37.0017) to (45.55, -36.5017)
  circle C2 centre (50, -18.6888) radius 2.7
  arc A3 centre (46.05, -36.5017) radius 0.7 clockwise from (46.05, -37.2017) to (45.35, -36.5017)
  arc A4 centre (53.95, -36.5017) radius 0.7 clockwise from (54.65, -36.5017) to (53.95, -37.2017)
  circle C3 centre (50, -20.3288) radius 2.7
  point P2 (50, -18.6888)
  point P31 (50, -18.6888)
  point P30 (50, -20.3288)
  equal C2 C3
  coincident P2 P31
  vertical L13
  coincident P30 L13
  dimension "d5" = 0.2
  dimension "d6" = 0.2
  dimension "d74" distance P2 P30 = 1.64
extrude "Extrude2" new body sketch "Sketch1" profile of L1 L2 L3 L4 against normal blind 1
extrude "Extrude3" cut sketch "Sketch2" profile of L1 L2 A1 A2 L3 L4 L6 L8 A4 L7 L5 A3 against normal blind 1
fillet "Fillet1" radius 5
fillet "Fillet2" radius 5
position "Position2"
sketch "Sketch3" plane through (0, 0, 0) normal (0, 1, 0) x axis (-1, 0, 0)
  line L1 (-54.65, 36.5017) -> (-54.65, 25.9017)
  line L2 (-46.05, 37.2017) -> (-53.95, 37.2017)
  line L3 (-45.35, 25.9017) -> (-45.35, 36.5017)
  line L4 (-54.65, 25.9017) -> (-45.35, 25.9017)
  line L5 (-105, 40) -> (-5, 40)
  line L6 (-110, 5) -> (-110, 35)
  line L7 (-5, 0) -> (-105, 0)
  line L8 (0, 35) -> (0, 5)
  arc A1 centre (-53.95, 36.5017) radius 0.7 clockwise from (-54.65, 36.5017) to (-53.95, 37.2017)
  arc A2 centre (-46.05, 36.5017) radius 0.7 clockwise from (-46.05, 37.2017) to (-45.35, 36.5017)
  arc A3 centre (-5, 35) radius 5 clockwise from (-5, 40) to (0, 35)
  arc A4 centre (-105, 35) radius 5 clockwise from (-110, 35) to (-105, 40)
  arc A5 centre (-105, 5) radius 5 clockwise from (-105, 0) to (-110, 5)
  arc A6 centre (-5, 5) radius 5 clockwise from (0, 5) to (-5, 0)
  circle C1 centre (-50, 15.6888) radius 2
  circle C2 centre (-50, 15.6888) radius 2.5
  circle C3 centre (-50, 15.6888) radius 2
  circle C4 centre (-50, 15.6888) radius 2.7
  circle C5 centre (-50, 17.3288) radius 2.7
  point P24 (-50, 15.6888)
  point P25 (-50, 17.3288)
  equal C4 C5
  dimension "d15" = 0.2
  dimension "d75" distance P24 P25 = 1.64
extrude "Extrude4" cut sketch "Sketch3" profile of C1 C2 C3 C4 C5 against normal blind 2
